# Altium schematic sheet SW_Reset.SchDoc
size A4
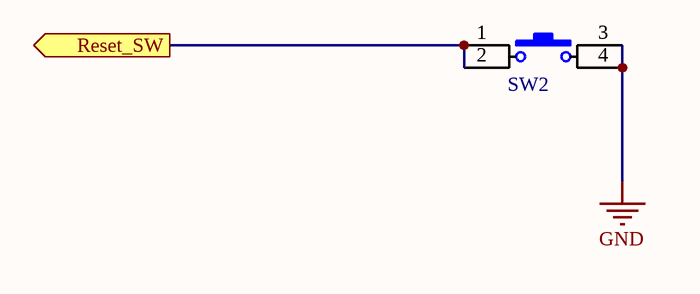
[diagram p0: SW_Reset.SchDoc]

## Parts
SW2  Aus Datenbank  [MECH_TASTER_FSM6JSMA]  (value not drawn)

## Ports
Reset_SW (out)

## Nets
GND: SW2.3(-) SW2.4(-)
Reset_SW: SW2.1(-) SW2.2(-) ; port Reset_SW

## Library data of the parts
SW2 = MECH_TASTER_FSM6JSMA: SPNO, SMD, 6x6mm, H=3,57mm; H_Temp_min: -35°C; I_Temp_max: 85°C; D_Hersteller: TYCO ELECTRONICS; B_Bestellnummer: 1555991; X_Datenblatt: S:\Datenblaetter\_RUETZ_ALTIUM_LIB\RUETZ_IC\IC_??.pdf; J_Richtpreis_10: 0,20€; K_Richtpreis_100: 0,19€; W_Erstellt: MRipel; W_Geprueft: bitte Ausfüllen; W_Info: optional; L_Spannung: 24V max; G_Wird_beigestellt: nein; A_Update_From_DB: Ja; A_Database_ID: not updated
